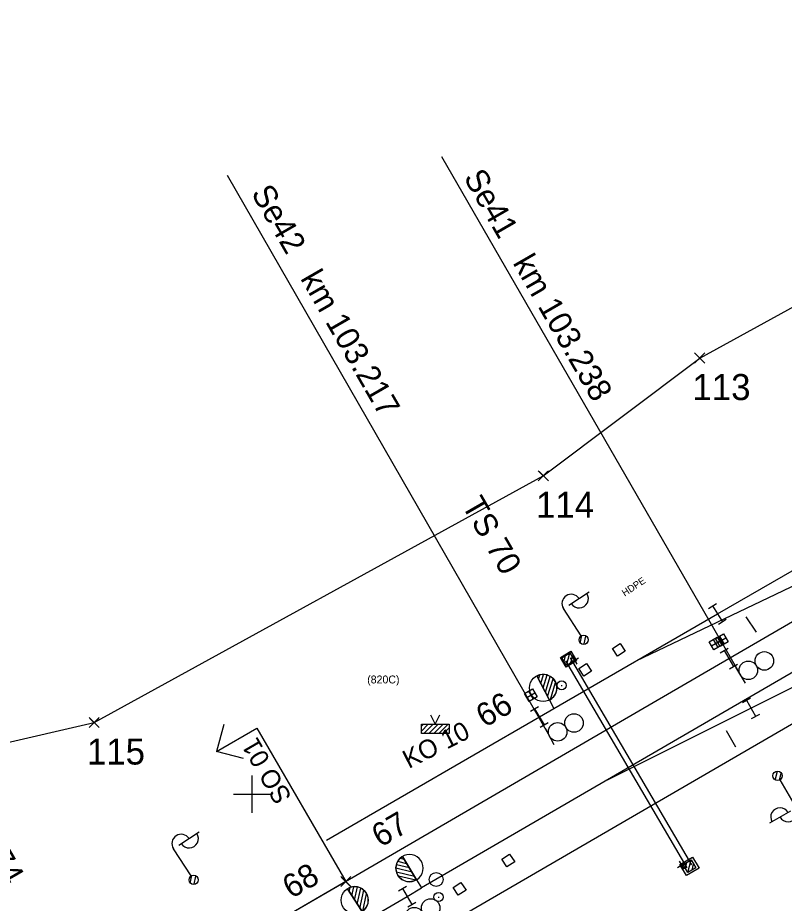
# Model space of a CAD drawing. Extents: x -566182 to -565305, y -1203073 to -1202401.
# Drawn here: x -565725.2 to -565642.7, y -1202711.7 to -1202616.5 of the extents above; entities that cross this region are included whole.
import ezdxf

# ---------------------------------------------------------------- set-up
doc = ezdxf.new("R2010")
doc.units = 0
for name, color, linetype in [('CD', 7, 'Continuous'), ('LÁTAL_SVRŠEK', 7, 'Continuous'), ('Vrstva 1', 7, 'Continuous'), ('Vrstva 10', 7, 'Continuous'), ('Vrstva 12', 7, 'Continuous'), ('Vrstva 13', 7, 'Continuous'), ('Vrstva 16', 7, 'Continuous'), ('Vrstva 17', 7, 'Continuous'), ('Vrstva 18', 7, 'Continuous'), ('Vrstva 22', 7, 'Continuous'), ('Vrstva 24', 7, 'Continuous'), ('Vrstva 25', 7, 'Continuous'), ('Vrstva 40', 7, 'Continuous'), ('Vrstva 42', 7, 'Continuous'), ('Vrstva 5', 7, 'Continuous'), ('Vrstva 6', 7, 'Continuous'), ('Vrstva 60', 7, 'Continuous'), ('Vrstva 62', 7, 'Continuous'), ('Vrstva 8', 7, 'Continuous'), ('Vrstva 9', 7, 'Continuous')]:
    doc.layers.add(name, color=color, linetype=linetype)

# ---------------------------------------------------------------- blocks, each defined once
blk = doc.blocks.new('EOV')
at = {"layer": 'Vrstva 62'}
blk.add_lwpolyline([(-5, 5), (5, 5), (5, -5), (-5, -5)], close=True, dxfattribs=at)
blk = doc.blocks.new('C513')
at = {"layer": 'Vrstva 6'}
blk.add_circle((0, 0), 7.5, dxfattribs=at)
blk = doc.blocks.new('C53')
at = {"layer": 'Vrstva 22'}
blk.add_line((-0.5, 0), (0.5, 0), dxfattribs=at)
blk.add_circle((0, 0), 5, dxfattribs=at)
blk = doc.blocks.new('C649')
at = {"layer": 'Vrstva 18'}
for p, q in [((-5, 10), (5, 10)), ((0, 10), (0, -10)), ((-5, -10), (5, -10))]:
    blk.add_line(p, q, dxfattribs=at)
blk = doc.blocks.new('C515_2')
at = {"layer": 'Vrstva 8'}
for p, q in [((-0.02, 39.56), (-0.02, 10.29)), ((-0.02, 35.76), (3.35, 39.12)), ((-0.03, 19.84), (12.52, 32.4)), ((-0.02, 30.46), (7.16, 37.63)), ((-0.02, 25.14), (10.19, 35.36)), ((-0.02, 14.54), (14.1, 28.67)), ((1.11, 10.37), (14.53, 23.79)), ((-0.04, 10.28), (0, 0))]:
    blk.add_line(p, q, dxfattribs=at)
for points in [[(-0.03, 10.29), (-0.02, 39.56)], [(-0.02, 10.29), (-0.03, 10.29)]]:
    blk.add_lwpolyline(points, dxfattribs=at)
blk.add_circle((-0.01, 25.01), 14.62, dxfattribs=at)
blk.add_arc((-0.02, 24.93), 14.63, 270.02531, 89.98616, dxfattribs=at)
blk = doc.blocks.new('C515_3')
at = {"layer": 'Vrstva 8'}
for p, q in [((-0.02, 39.56), (-0.02, 10.29)), ((-0.02, 35.76), (3.35, 39.13)), ((-0.03, 19.84), (12.53, 32.39)), ((-0.03, 14.54), (14.1, 28.67)), ((-0.02, 30.45), (7.16, 37.63)), ((-0.02, 25.15), (10.19, 35.36)), ((1.1, 10.37), (14.52, 23.79)), ((-0.04, 10.27), (0, 0))]:
    blk.add_line(p, q, dxfattribs=at)
for points in [[(-0.03, 10.29), (-0.02, 39.56)], [(-0.02, 10.29), (-0.03, 10.29)]]:
    blk.add_lwpolyline(points, dxfattribs=at)
blk.add_circle((-0.01, 25), 14.62, dxfattribs=at)
blk.add_arc((-0.03, 24.93), 14.63, 270.01183, 89.97268, dxfattribs=at)
blk = doc.blocks.new('C515_4')
at = {"layer": 'Vrstva 8'}
for p, q in [((-0.03, 35.76), (3.35, 39.13)), ((-0.02, 39.56), (-0.02, 10.29)), ((-0.03, 19.84), (12.53, 32.4)), ((-0.03, 14.54), (14.1, 28.67)), ((-0.02, 30.44), (7.16, 37.63)), ((-0.02, 25.15), (10.19, 35.36)), ((1.1, 10.37), (14.53, 23.79)), ((-0.03, 10.28), (0, 0))]:
    blk.add_line(p, q, dxfattribs=at)
for points in [[(-0.03, 10.28), (-0.02, 39.56)], [(-0.02, 10.29), (-0.03, 10.28)]]:
    blk.add_lwpolyline(points, dxfattribs=at)
blk.add_circle((-0.01, 25), 14.62, dxfattribs=at)
blk.add_arc((-0.03, 24.93), 14.63, 270.01187, 89.97272, dxfattribs=at)
blk = doc.blocks.new('C691')
at = {"layer": 'Vrstva 12'}
for p, q in [((-5, 0), (5, 0)), ((0, 5), (0, -5))]:
    blk.add_line(p, q, dxfattribs=at)
blk = doc.blocks.new('C669_1')
at = {"layer": 'Vrstva 6'}
for p, q in [((0, 5), (0, 40.01)), ((7, 40.01), (33.01, 40.01)), ((-5, -0.99), (1, 5)), ((-2, -4), (4.01, 2))]:
    blk.add_line(p, q, dxfattribs=at)
blk.add_circle((0, 0), 5, dxfattribs=at)
blk.add_circle((0, 0), 5, dxfattribs=at)
for centre, start, end in [((10, 40.01), 0.00003, 180.00003), ((20, 39.89), 179.29745, 0.7026)]:
    blk.add_arc(centre, 10, start, end, dxfattribs=at)
blk = doc.blocks.new('C669')
at = {"layer": 'Vrstva 6'}
for p, q in [((0, 5), (0, 40.01)), ((7, 40.01), (33, 40.01)), ((-5, -1), (1, 5)), ((-2, -4), (4.01, 2))]:
    blk.add_line(p, q, dxfattribs=at)
blk.add_circle((0, 0), 5, dxfattribs=at)
blk.add_circle((0, 0), 5, dxfattribs=at)
for centre, start, end in [((10, 40.01), 0.00006, 180.00006), ((20, 39.89), 179.29748, 0.70263)]:
    blk.add_arc(centre, 10, start, end, dxfattribs=at)
blk = doc.blocks.new('C661_2')
at = {"layer": 'Vrstva 12'}
for p, q in [((-5.01, 0.33), (-0.33, 4.99)), ((-5, -4.96), (4.96, 5)), ((0.27, -5), (5, -0.27))]:
    blk.add_line(p, q, dxfattribs=at)
blk.add_lwpolyline([(-5, 5), (5, 5), (5, -5), (-5, -5)], close=True, dxfattribs=at)
blk.add_lwpolyline([(-5, 5), (5, 5), (5, -5), (-5, -5), (-5, 5)], dxfattribs=at)
blk = doc.blocks.new('C534')
at = {"layer": 'Vrstva 16'}
for p, q in [((-15, 2.82), (-12.82, 5)), ((-15, -2.48), (-7.52, 5)), ((-12.2, -5), (-2.2, 5)), ((-6.92, -5), (3.08, 5)), ((-1.6, -5), (8.4, 5)), ((3.7, -5), (13.7, 5)), ((9, -5), (15, 1)), ((14.3, -5), (15, -4.3))]:
    blk.add_line(p, q, dxfattribs=at)
for points in [[(-5, 15), (0, 5), (5, 15)], [(-15, 5), (15, 5), (15, -5), (-15, -5), (-15, 5)]]:
    blk.add_lwpolyline(points, dxfattribs=at)
blk.add_lwpolyline([(-15, 5), (15, 5), (15, -5), (-15, -5)], close=True, dxfattribs=at)
blk = doc.blocks.new('C575')
at = {"layer": 'Vrstva 24'}
blk.add_line((0, 10), (0.01, -10), dxfattribs=at)
for centre in [(10, -0.01), (30, -0.01)]:
    blk.add_circle(centre, 10, dxfattribs=at)
blk = doc.blocks.new('C575_3')
at = {"layer": 'Vrstva 24'}
blk.add_line((0.01, 10), (0, -10), dxfattribs=at)
for centre in [(10, 0), (30, 0)]:
    blk.add_circle(centre, 10, dxfattribs=at)
blk = doc.blocks.new('C575_4')
at = {"layer": 'Vrstva 24'}
blk.add_line((-0.01, 9.99), (0, -10), dxfattribs=at)
for centre in [(10, 0), (30, 0)]:
    blk.add_circle(centre, 10, dxfattribs=at)
blk = doc.blocks.new('STTRAN')
at = {"layer": 'Vrstva 40'}
for p, q in [((-5, 0), (5, 0)), ((0, 5), (0, -5))]:
    blk.add_line(p, q, dxfattribs=at)
blk.add_lwpolyline([(-4.99, 5), (5, 4.99), (4.99, -5), (-5, -4.99)], close=True, dxfattribs=at)
blk = doc.blocks.new('EOV_1')
at = {"layer": 'Vrstva 40'}
blk.add_lwpolyline([(-5, 5), (5, 5), (5, -5), (-5, -5)], close=True, dxfattribs=at)

msp = doc.modelspace()

# ---------------------------------------------------------------- linework, layer by layer
at = {"layer": 'CD'}
for p, q in [((-565651.82, -1202653.08), (-565584.94, -1202616.47)), ((-565668.65, -1202665.75), (-565651.82, -1202653.08)), ((-565716.98, -1202692.29), (-565668.65, -1202665.75)), ((-565769.79, -1202704.47), (-565716.98, -1202692.29))]:
    msp.add_line(p, q, dxfattribs=at)
at = {"layer": 'LÁTAL_SVRŠEK'}
msp.add_line((-565689.904, -1202709.396), (-565723.905, -1202729.137), dxfattribs=at)
at = {"layer": 'Vrstva 1'}
for p, q in [((-565703.04, -1202692.506), (-565703.809, -1202695.406)), ((-565703.809, -1202695.406), (-565699.485, -1202692.895)), ((-565699.485, -1202692.895), (-565689.904, -1202709.396)), ((-565700.91, -1202696.175), (-565703.809, -1202695.406))]:
    msp.add_line(p, q, dxfattribs=at)
at = {"layer": 'Vrstva 10'}
for p, q in [((-565666.815, -1202685.311), (-565665.674, -1202684.623)), ((-565665.674, -1202684.623), (-565665.06, -1202685.652)), ((-565666.195, -1202686.331), (-565666.815, -1202685.311)), ((-565665.06, -1202685.652), (-565666.195, -1202686.331))]:
    msp.add_line(p, q, dxfattribs=at)
for points in [[(-565645.711, -1202682.579), (-565646.829, -1202680.921)], [(-565647.939, -1202694.931), (-565648.921, -1202693.189)], [(-565653.231, -1202708.761), (-565653.943, -1202707.556), (-565652.601, -1202706.762), (-565651.888, -1202707.967)], [(-565651.888, -1202707.967), (-565653.231, -1202708.761)]]:
    msp.add_lwpolyline(points, dxfattribs=at)
at = {"layer": 'Vrstva 12'}
for points in [[(-565653.172, -1202707.906), (-565666.23, -1202685.638)], [(-565652.654, -1202707.602), (-565665.712, -1202685.334)]]:
    msp.add_lwpolyline(points, dxfattribs=at)
at = {"layer": 'Vrstva 5'}
for p, q in [((-565700, -1202698), (-565700, -1202702)), ((-565702, -1202700), (-565698, -1202700))]:
    msp.add_line(p, q, dxfattribs=at)
at = {"layer": 'Vrstva 6'}
for points in [[(-565772.18, -1202757.12), (-565716.36, -1202724.73), (-565690.38, -1202709.64), (-565661.87, -1202693.06), (-565648.68, -1202685.41), (-565628.31, -1202673.57)], [(-565685.66, -1202717.86), (-565678.55, -1202713.73), (-565657.5, -1202701.52), (-565621, -1202680.32)], [(-565691.99, -1202704.95), (-565676.12, -1202695.76), (-565669.07, -1202691.68), (-565667.5, -1202690.78)], [(-565687.59, -1202713.5), (-565683.3, -1202711), (-565681.75, -1202710.09)]]:
    msp.add_lwpolyline(points, dxfattribs=at)
at = {"layer": 'Vrstva 60'}
for p, q in [((-565679.614, -1202631.414), (-565647.34, -1202687.32)), ((-565702.671, -1202633.412), (-565667.986, -1202693.76)), ((-565651.37, -1202653.53), (-565652.37, -1202652.53)), ((-565651.37, -1202652.63), (-565652.37, -1202653.63)), ((-565652.27, -1202653.53), (-565651.27, -1202652.53)), ((-565652.27, -1202652.63), (-565651.27, -1202653.63)), ((-565651.82, -1202653.08), (-565651.82, -1202653.08)), ((-565668.2, -1202666.2), (-565669.2, -1202665.2)), ((-565668.2, -1202665.3), (-565669.2, -1202666.3)), ((-565669.1, -1202666.2), (-565668.1, -1202665.2)), ((-565669.1, -1202665.3), (-565668.1, -1202666.3)), ((-565668.65, -1202665.75), (-565668.65, -1202665.75)), ((-565716.53, -1202692.74), (-565717.53, -1202691.74)), ((-565716.53, -1202691.84), (-565717.53, -1202692.84)), ((-565717.43, -1202692.74), (-565716.43, -1202691.74)), ((-565717.43, -1202691.84), (-565716.43, -1202692.84)), ((-565716.98, -1202692.29), (-565716.98, -1202692.29)), ((-565689.454, -1202709.846), (-565690.454, -1202708.846)), ((-565689.454, -1202708.946), (-565690.454, -1202709.946)), ((-565690.354, -1202709.846), (-565689.354, -1202708.846)), ((-565690.354, -1202708.946), (-565689.354, -1202709.946)), ((-565689.904, -1202709.396), (-565689.904, -1202709.396))]:
    msp.add_line(p, q, dxfattribs=at)
at = {"layer": 'Vrstva 8'}
for points in [[(-565667.5, -1202690.78), (-565649.91, -1202680.6), (-565639.25, -1202674.45)], [(-565638.11, -1202675.88), (-565658.705, -1202685.69)], [(-565634.87, -1202682.87), (-565681.75, -1202710.09)], [(-565633.95, -1202684.58), (-565661.783, -1202698.496)]]:
    msp.add_lwpolyline(points, dxfattribs=at)

# ---------------------------------------------------------------- block references
at = {"layer": 'Vrstva 12'}
for name, p, xscale, yscale, rotation in [('C661_2', (-565665.971, -1202685.486), 0.10000022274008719, 0.10000022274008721, 30.88967668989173), ('C691', (-565665.281, -1202685.597), 0.09999990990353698, 0.09999990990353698, 30.000029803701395), ('C691', (-565653.783, -1202707.629), 0.09999990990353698, 0.09999990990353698, 30.000029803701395), ('C661_2', (-565652.913, -1202707.754), 0.10000023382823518, 0.10000023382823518, 30.59321761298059)]:
    msp.add_blockref(name, p, dxfattribs=dict(at, xscale=xscale, yscale=yscale, rotation=rotation))
at = {"layer": 'Vrstva 16', "xscale": 0.1, "yscale": 0.10000000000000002}
msp.add_blockref('C534', (-565680.27, -1202692.96), dxfattribs=at)
at = {"layer": 'Vrstva 18'}
for p, xscale, yscale, rotation in [((-565649.91, -1202680.6), 0.1000000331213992, 0.1000000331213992, 32.22770254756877), ((-565648.68, -1202685.41), 0.10000003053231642, 0.10000003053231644, 30.576240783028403), ((-565669.07, -1202691.68), 0.10000004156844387, 0.10000004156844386, 31.251383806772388), ((-565646.29, -1202690.75), 0.10000019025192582, 0.10000019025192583, 29.3226109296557), ((-565683.3, -1202711), 0.09999990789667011, 0.09999990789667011, 30.81706047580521)]:
    msp.add_blockref('C649', p, dxfattribs=dict(at, xscale=xscale, yscale=yscale, rotation=rotation))
at = {"layer": 'Vrstva 22', "xscale": 0.1, "yscale": 0.10000000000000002}
for p in [(-565666.67, -1202688.29), (-565679.92, -1202711.06)]:
    msp.add_blockref('C53', p, dxfattribs=at)
at = {"layer": 'Vrstva 24'}
for name, p, xscale, yscale, rotation in [('C575_3', (-565647.449, -1202687.188), 0.1000000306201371, 0.1000000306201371, 30.583058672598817), ('C575_4', (-565667.986, -1202693.76), 0.09999989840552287, 0.09999989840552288, 28.136677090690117), ('C575', (-565683.419, -1202713.646), 0.09999995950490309, 0.09999995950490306, 27.86681136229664)]:
    msp.add_blockref(name, p, dxfattribs=dict(at, xscale=xscale, yscale=yscale, rotation=rotation))
at = {"layer": 'Vrstva 40'}
for name, p, xscale, yscale, rotation in [('STTRAN', (-565649.442, -1202683.424), 0.09999990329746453, 0.09999990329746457, 30.059200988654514), ('EOV_1', (-565660.524, -1202684.478), 0.10000003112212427, 0.10000003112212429, 32.99994277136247), ('STTRAN', (-565650.119, -1202683.784), 0.09999990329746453, 0.09999990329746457, 30.059200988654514), ('EOV_1', (-565664.145, -1202686.621), 0.10000003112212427, 0.10000003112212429, 32.99994277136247), ('STTRAN', (-565669.997, -1202689.337), 0.09999990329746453, 0.09999990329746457, 30.059200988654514), ('EOV_1', (-565672.417, -1202707.13), 0.10000003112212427, 0.10000003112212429, 32.99994277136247), ('EOV_1', (-565677.652, -1202710.179), 0.10000003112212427, 0.10000003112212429, 32.99994277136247)]:
    msp.add_blockref(name, p, dxfattribs=dict(at, xscale=xscale, yscale=yscale, rotation=rotation))
at = {"layer": 'Vrstva 6'}
for name, p, xscale, yscale, rotation in [('C669', (-565664.303, -1202683.397), 0.10000003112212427, 0.10000003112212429, 32.99994277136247), ('C669_1', (-565643.44, -1202698.014), 0.09999990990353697, 0.099999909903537, -149.99997019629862), ('C669', (-565706.274, -1202709.217), 0.10000003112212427, 0.10000003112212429, 32.99994277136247), ('C513', (-565680.171, -1202709.183), 0.1, 0.10000000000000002, 180)]:
    msp.add_blockref(name, p, dxfattribs=dict(at, xscale=xscale, yscale=yscale, rotation=rotation))
at = {"layer": 'Vrstva 62', "xscale": 0.10000003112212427, "yscale": 0.10000003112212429, "rotation": 32.99994277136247}
for p in [(-565660.524, -1202684.478), (-565664.145, -1202686.621), (-565672.417, -1202707.13), (-565677.652, -1202710.179)]:
    msp.add_blockref('EOV', p, dxfattribs=at)
at = {"layer": 'Vrstva 8'}
for name, p, xscale, yscale, rotation in [('C515_4', (-565667.5, -1202690.78), 0.10000012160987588, 0.10000012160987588, 27.726816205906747), ('C515_3', (-565681.75, -1202710.09), 0.10000003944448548, -0.10000003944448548, -148.73987656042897), ('C515_2', (-565687.59, -1202713.5), 0.09999974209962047, 0.09999974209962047, 32.807156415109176)]:
    msp.add_blockref(name, p, dxfattribs=dict(at, xscale=xscale, yscale=yscale, rotation=rotation))

# ---------------------------------------------------------------- texts
at = {"layer": 'Vrstva 1'}
msp.add_text('SO 01', height=2, rotation=120.13913, dxfattribs=at).set_placement((-565695.669, -1202700.299))
at = {"layer": 'Vrstva 13'}
for s, p in [('TS 70', (-565677.483, -1202668.892)), ('TS 74', (-565731.012, -1202702.236))]:
    msp.add_text(s, height=2.5, rotation=300, dxfattribs=at).set_placement(p)
at = {"layer": 'Vrstva 17'}
msp.add_text('KO 10', height=2, rotation=27.02852, dxfattribs=at).set_placement((-565683.129, -1202697.298))
at = {"layer": 'Vrstva 25'}
for s, p in [('Se41   km 103.238', (-565677.28, -1202633.661)), ('Se42   km 103.217', (-565700.141, -1202635.336))]:
    msp.add_text(s, height=2.5, rotation=299.98733, dxfattribs=at).set_placement(p)
at = {"layer": 'Vrstva 42'}
msp.add_text('HDPE', height=0.75, rotation=33.60443, dxfattribs=at).set_placement((-565659.887, -1202678.756))
at = {"layer": 'Vrstva 60'}
for s, p in [('113', (-565652.598, -1202657.6)), ('114', (-565669.428, -1202670.27)), ('115', (-565717.758, -1202696.81))]:
    msp.add_text(s, height=2.8, dxfattribs=at).set_placement(p)
at = {"layer": 'Vrstva 9'}
msp.add_text('(820C)', height=0.85, dxfattribs=at).set_placement((-565687.599, -1202688.084))
for s, rotation, p in [('66', 30.1449, (-565674.949, -1202692.893)), ('67', 30.14482, (-565686.176, -1202705.777)), ('68', 30.14484, (-565695.774, -1202711.296))]:
    msp.add_text(s, height=2.5, rotation=rotation, dxfattribs=at).set_placement(p)

doc.saveas('drawing.dxf')
